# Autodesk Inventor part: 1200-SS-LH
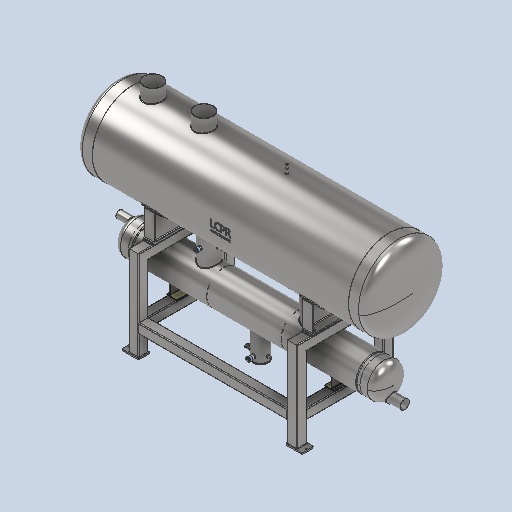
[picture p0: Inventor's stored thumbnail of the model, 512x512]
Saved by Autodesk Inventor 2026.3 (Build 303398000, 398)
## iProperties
Created: 2026-05
Part Number: 1200-SS-LH
Material: Generic
Document SubType Name: Modeling
Designer: rva
Density: 1 g/cm^3
Appearance: Default
Author: rva
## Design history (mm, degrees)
derived "LCPR-SS-1200-LH.iam"
body "Solid1"
node "Sub-SS-500-250-3326-294-125-100-LH.iam:1::LCPR-SS-500 mm Sub"
node "Sub-SS-500-250-3326-294-125-100-LH.iam:1::LCPR-SS-500 mm Sub"
node "Sub-SS-500-250-3326-294-125-100-LH.iam:1::H1100-R.ipt:1"
node "Sub-SS-500-250-3326-294-125-100-LH.iam:1::1-2 Inch NPT Socke"
node "Sub-SS-500-250-3326-294-125-100-LH.iam:1::Welds"
node "Sub-SS-500-250-3326-294-125-100-LH.iam:1::200 mm Oil Pot Ass"
node "LCPR-SS-1200-Frame Assembly.iam:1::LCPR-SS_170 x 250 Foot Pl"
node "LCPR-SS-1200-Frame Assembly.iam:1::LCPR-SS_170 x 250 Foot Pl"
node "LCPR-SS-1200-Frame Assembly.iam:1::LCPR-SS_170 x 250 Foot Pl"
node "LCPR-SS-1200-Frame Assembly.iam:1::LCPR-SS_170 x 250 Foot Pl"
node "LCPR-SS-1200-Frame Assembly.iam:1::Welds"
node "AS 1112 - M20(2).ipt:1"
node "AS 1237 (4.2) 20 mm:1"
node "AS 1111 - Metric M20 x 200:1"
node "AS 1112 - M20(2).ipt:2"
node "AS 1237 (4.2) 20 mm:3"
node "AS 1111 - Metric M20 x 200:2"
node "AS 1112 - M20(2).ipt:3"
node "AS 1237 (4.2) 20 mm:5"
node "AS 1111 - Metric M20 x 200:3"
node "AS 1112 - M20(2).ipt:4"
node "AS 1237 (4.2) 20 mm:7"
node "AS 1111 - Metric M20 x 200:4"
node "Nylon Heat Tranfer Spacer 1028 x 150.ipt:1"
node "Nylon Heat Tranfer Spacer 1028 x 150.ipt:2"
node "LCPR-SS-1200-3800-250-WELD.iam:1::ASME B36.10M Pipe 48x0.375"
node "LCPR-SS-1200-3800-250-WELD.iam:1::LCPR-LOGO.ipt:1"
node "LCPR-SS-1200-3800-250-WELD.iam:1::H1100-R.ipt:1"
node "LCPR-SS-1200-3800-250-WELD.iam:1::1200 mm-SS-Dome End Cap S1"
node "LCPR-SS-1200-3800-250-WELD.iam:1::LCPR-SS-1200-Leg Assembly."
node "LCPR-SS-1200-3800-250-WELD.iam:1::LCPR-SS-1200-Leg Assembly."
node "LCPR-SS-1200-3800-250-WELD.iam:1::1200 mm-SS-Dome End Cap S1"
node "LCPR-SS-1200-3800-250-WELD.iam:1::Welds"
node "Nylon Heat Tranfer Spacer 300 x 150.ipt:1"
node "Nylon Heat Tranfer Spacer 300 x 150.ipt:2"
node "LCPR-SS-1200-LH.iam_Bodies"
